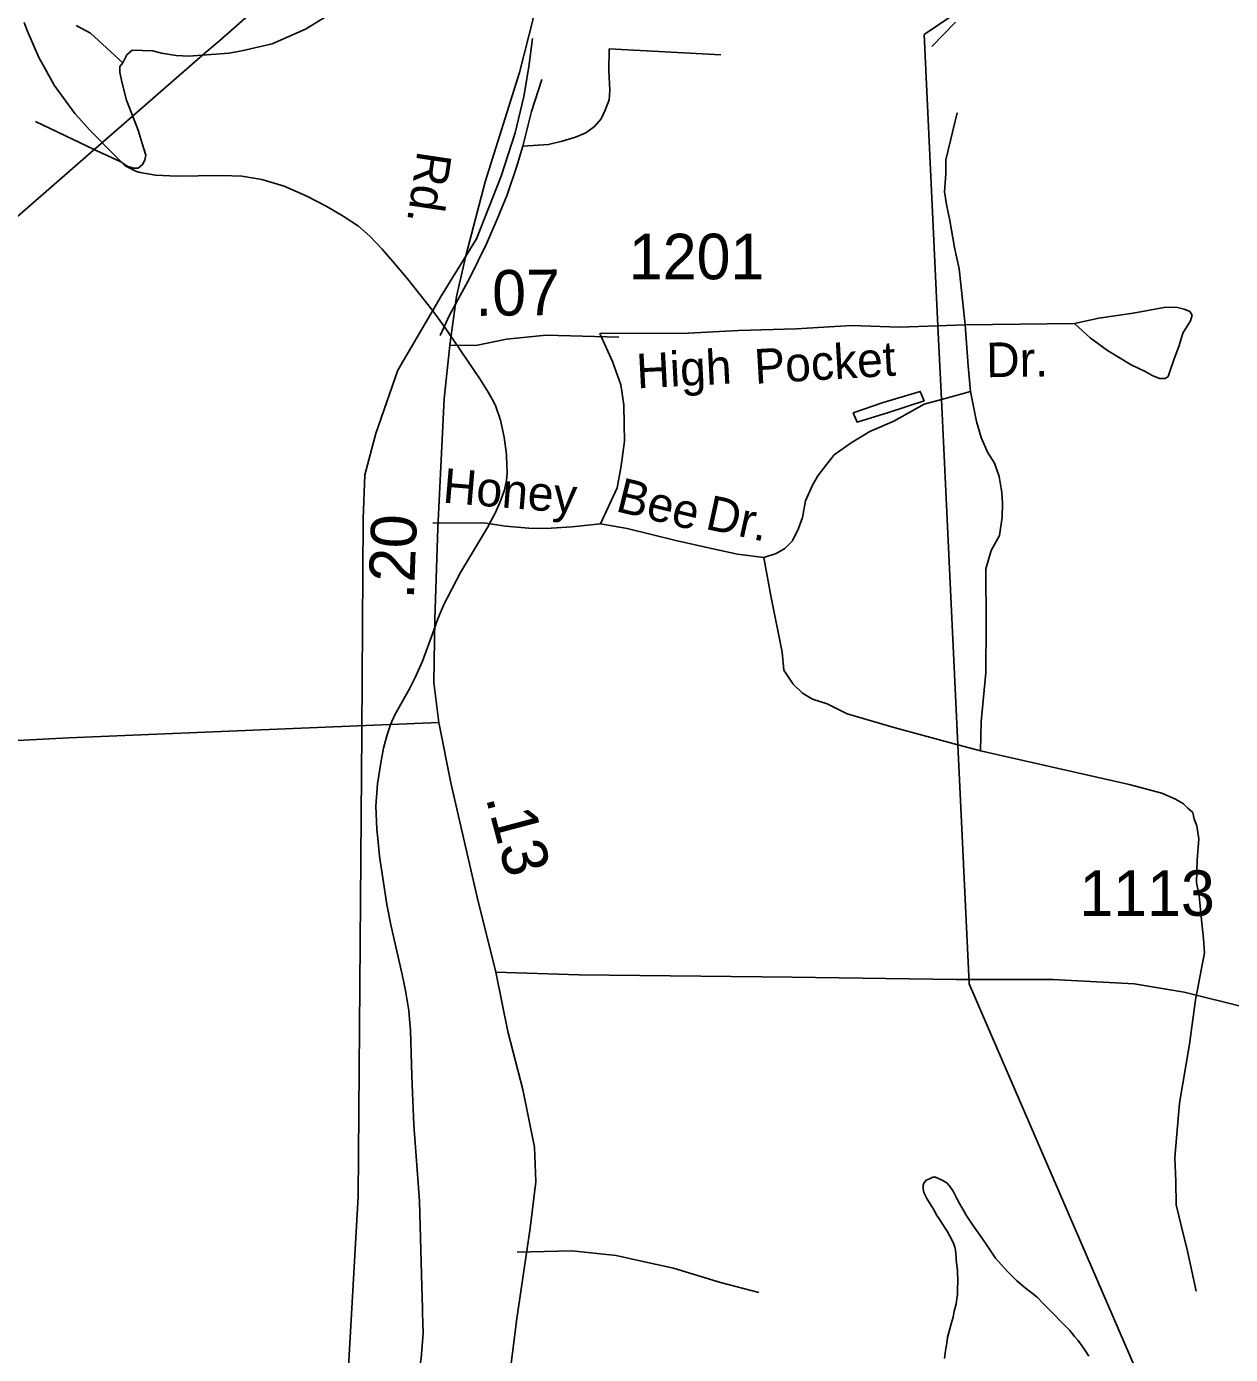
# Model space of a CAD drawing. Extents: x 2001466 to 2224147, y 644118 to 847247.
# Drawn here: x 2045971 to 2049275, y 678885 to 682530 of the extents above; entities that cross this region are included whole.
import ezdxf

# ---------------------------------------------------------------- set-up
doc = ezdxf.new("R2010")
doc.units = 0
for name, color, linetype in [('Exist Hydrographic Misc Water Feature', 7, 'Continuous'), ('Exist Railroad Mainline', 7, 'Continuous'), ('Exist Road Non-System Type 51', 7, 'Continuous'), ('Exist Road Non-System Type 51 Label', 7, 'Continuous'), ('Exist Road Secondary Mileage Hundredths English Label', 7, 'Continuous'), ('Exist Road Secondary Type 51 Attributed', 7, 'Continuous'), ('Exist Road Secondary Type 51 Label', 7, 'Continuous'), ('Exist Road Secondary Type 51 Number Label', 7, 'Continuous'), ('Exist Utilities Electrical Transmission Line', 7, 'Continuous')]:
    doc.layers.add(name, color=color, linetype=linetype)

msp = doc.modelspace()

# ---------------------------------------------------------------- linework, layer by layer
at = {"layer": 'Exist Hydrographic Misc Water Feature'}
for p, q in [((2045964.4, 682541.2), (2045972.8, 682519.2)), ((2046272.4, 682132.1), (2046282.4, 682129.5)), ((2046272.4, 682132.1), (2046282.4, 682129.5)), ((2046839.9, 682009.5), (2046842.8, 682007.8)), ((2047271.8, 681449.6), (2047281.8, 681403)), ((2047283.7, 681263), (2047282.9, 681258))]:
    msp.add_line(p, q, dxfattribs=at)
for points in [[(2045972.8, 682519.2), (2046005, 682445.2), (2046020.4, 682417.4)], [(2045972.8, 682519.2), (2046005, 682445.2), (2046020.4, 682417.4)], [(2046020.4, 682417.4), (2046046.8, 682369.7), (2046103.8, 682291.6), (2046114.5, 682279.6)], [(2046020.4, 682417.4), (2046046.8, 682369.7), (2046103.8, 682291.6), (2046114.5, 682279.6)], [(2046114.5, 682279.6), (2046144, 682246.8), (2046210.4, 682179.4)], [(2046114.5, 682279.6), (2046144, 682246.8), (2046210.4, 682179.4)], [(2046210.4, 682179.4), (2046241.8, 682147.6), (2046272.4, 682132.1)], [(2046210.4, 682179.4), (2046241.8, 682147.6), (2046272.4, 682132.1)], [(2046282.4, 682129.5), (2046324.9, 682122.3), (2046383.9, 682119.3), (2046441.7, 682120.1)], [(2046282.4, 682129.5), (2046324.9, 682122.3), (2046383.9, 682119.3), (2046441.7, 682120.1)], [(2046441.7, 682120.1), (2046505.9, 682121), (2046561.9, 682119.4), (2046578.3, 682116.8)], [(2046441.7, 682120.1), (2046505.9, 682121), (2046561.9, 682119.4), (2046578.3, 682116.8)], [(2046578.3, 682116.8), (2046616.8, 682110.8), (2046677.7, 682091.8), (2046739.9, 682064.8), (2046794.8, 682036.3), (2046839.9, 682009.5)], [(2046578.3, 682116.8), (2046616.8, 682110.8), (2046677.7, 682091.8), (2046739.9, 682064.8), (2046794.8, 682036.3), (2046839.9, 682009.5)], [(2046842.8, 682007.8), (2046881.8, 681981.8), (2046912.7, 681955.1), (2046946.8, 681919.2), (2046975.7, 681885.2)], [(2046842.8, 682007.8), (2046881.8, 681981.8), (2046912.7, 681955.1), (2046946.8, 681919.2), (2046975.7, 681885.2)], [(2046975.7, 681885.2), (2047015.9, 681837.9), (2047086, 681749.9), (2047119.8, 681703.3), (2047145.3, 681665.8)], [(2046975.7, 681885.2), (2047015.9, 681837.9), (2047086, 681749.9), (2047119.8, 681703.3), (2047145.3, 681665.8)], [(2047145.3, 681665.8), (2047214.8, 681563.3), (2047233.4, 681533.4)], [(2047145.3, 681665.8), (2047214.8, 681563.3), (2047233.4, 681533.4)], [(2047233.4, 681533.4), (2047237.9, 681526.5), (2047248.4, 681507.2)], [(2047233.4, 681533.4), (2047237.9, 681526.5), (2047248.4, 681507.2)], [(2048239.6, 681470.2), (2048249.9, 681444.4), (2048335.8, 681470.7), (2048433.8, 681502.9), (2048423.4, 681528.8), (2048321.2, 681498.4), (2048239.6, 681470.2)], [(2047248.4, 681507.2), (2047257.6, 681490.2), (2047271.8, 681449.6)], [(2047248.4, 681507.2), (2047257.6, 681490.2), (2047271.8, 681449.6)], [(2047281.8, 681403), (2047287.8, 681355.3), (2047289.2, 681321.9)], [(2047281.8, 681403), (2047287.8, 681355.3), (2047289.2, 681321.9)], [(2047289.4, 681305.1), (2047288, 681284.1), (2047283.7, 681263)], [(2047289.4, 681305.1), (2047288, 681284.1), (2047283.7, 681263)], [(2047289.2, 681321.9), (2047289.8, 681310.2), (2047289.4, 681305.1)], [(2047289.2, 681321.9), (2047289.8, 681310.2), (2047289.4, 681305.1)], [(2047282.9, 681258), (2047272.8, 681229.9), (2047258, 681196.1), (2047244.9, 681172.6)], [(2047282.9, 681258), (2047272.8, 681229.9), (2047258, 681196.1), (2047244.9, 681172.6)], [(2047244.9, 681172.6), (2047235.7, 681155.3), (2047161.9, 681031.3), (2047125.8, 680962.4)], [(2047244.9, 681172.6), (2047235.7, 681155.3), (2047161.9, 681031.3), (2047125.8, 680962.4)], [(2047125.8, 680962.4), (2047118, 680947.2), (2047106.9, 680921.2)], [(2047125.8, 680962.4), (2047118, 680947.2), (2047106.9, 680921.2)], [(2047106.9, 680921.2), (2047099.7, 680904.6), (2047084.8, 680863)], [(2047106.9, 680921.2), (2047099.7, 680904.6), (2047084.8, 680863)], [(2047084.8, 680863), (2047057.7, 680787.6), (2047037.8, 680742.8)], [(2047084.8, 680863), (2047057.7, 680787.6), (2047037.8, 680742.8)], [(2047037.8, 680742.8), (2047021.8, 680712.3), (2046981.8, 680640.6)], [(2047037.8, 680742.8), (2047021.8, 680712.3), (2046981.8, 680640.6)], [(2046981.8, 680640.6), (2046969.7, 680614), (2046965.2, 680599.8)], [(2046981.8, 680640.6), (2046969.7, 680614), (2046965.2, 680599.8)], [(2046965.2, 680599.8), (2046959.7, 680582.6), (2046956.2, 680569.4)], [(2046965.2, 680599.8), (2046959.7, 680582.6), (2046956.2, 680569.4)], [(2046956.2, 680569.4), (2046950.9, 680548.8), (2046946.8, 680529)], [(2046956.2, 680569.4), (2046950.9, 680548.8), (2046946.8, 680529)], [(2046946.8, 680529), (2046943.7, 680514.8), (2046934.1, 680451.1), (2046929.8, 680390.3), (2046931.8, 680326.1), (2046934.5, 680301.2)], [(2046946.8, 680529), (2046943.7, 680514.8), (2046934.1, 680451.1), (2046929.8, 680390.3), (2046931.8, 680326.1), (2046934.5, 680301.2)], [(2046934.5, 680301.2), (2046939.8, 680252.9), (2046959.7, 680119.8), (2046970.6, 680063.8), (2047001.5, 679928.2), (2047006.2, 679905.9)], [(2046934.5, 680301.2), (2046939.8, 680252.9), (2046959.7, 680119.8), (2046970.6, 680063.8), (2047001.5, 679928.2), (2047006.2, 679905.9)], [(2047006.2, 679905.9), (2047012, 679878.3), (2047019.8, 679829.1), (2047022, 679805)], [(2047006.2, 679905.9), (2047012, 679878.3), (2047019.8, 679829.1), (2047022, 679805)], [(2047022, 679805), (2047024.7, 679775.1), (2047028.4, 679649.8)], [(2047022, 679805), (2047024.7, 679775.1), (2047028.4, 679649.8)], [(2047028.4, 679649.8), (2047029.8, 679603.4), (2047033.9, 679514.8), (2047049.7, 679305.4), (2047056.1, 679070.1)], [(2047028.4, 679649.8), (2047029.8, 679603.4), (2047033.9, 679514.8), (2047049.7, 679305.4), (2047056.1, 679070.1)], [(2048490.2, 678873.3), (2048492.3, 678895.4), (2048495.9, 678915.5), (2048498.2, 678931.3), (2048507.8, 678969.2), (2048514, 678987.4), (2048516, 679003.3), (2048522, 679023.5), (2048523.8, 679037.4), (2048525.9, 679049.6), (2048525.9, 679067.4), (2048526.1, 679083.3), (2048526.1, 679093.4), (2048525.9, 679105.2), (2048525.9, 679115.3), (2048521.6, 679143.6), (2048521.6, 679151.3), (2048519.9, 679171.4), (2048517.9, 679179.4), (2048515.8, 679187.5), (2048509.7, 679199.3), (2048503.5, 679211.2), (2048497.6, 679223.4), (2048491.6, 679231.2), (2048485.7, 679241.5), (2048475.6, 679257.2), (2048467.4, 679269.4), (2048461.3, 679281.3), (2048453.5, 679293.4), (2048441.6, 679313.1), (2048433.6, 679329.3), (2048431.6, 679339.3), (2048431.4, 679349.1), (2048433.2, 679355.3), (2048439.3, 679363.3), (2048449.2, 679367.1), (2048457.6, 679371.1), (2048465.2, 679371.1), (2048475.6, 679367.1), (2048483.4, 679363.1), (2048497.4, 679355.3), (2048505.6, 679345.1), (2048513.4, 679333.4), (2048523.6, 679313.2), (2048531.4, 679299.5), (2048543.5, 679277.3), (2048549.5, 679267.5), (2048569.6, 679237.3), (2048587.4, 679211.4), (2048603.8, 679187.5), (2048629.8, 679149.5), (2048661.6, 679113.8), (2048687.9, 679087.5), (2048711.7, 679067.7), (2048731.5, 679051.7), (2048744.1, 679041.7), (2048761.9, 679024), (2048780.1, 679005.8), (2048792, 678993.8), (2048806, 678977.9), (2048822.2, 678962.1), (2048833.7, 678950.2), (2048846.4, 678934.1), (2048856.2, 678924.1), (2048866.1, 678910), (2048876.1, 678895.9), (2048886.2, 678880.2)], [(2047056.1, 679070.1), (2047057.7, 679012.7), (2047057.9, 678998.8)], [(2047056.1, 679070.1), (2047057.7, 679012.7), (2047057.9, 678998.8)], [(2047057.9, 678998.8), (2047058.9, 678944), (2047054, 678873.3), (2047039.7, 678795.8), (2047033.9, 678774.6)], [(2047057.9, 678998.8), (2047058.9, 678944), (2047054, 678873.3), (2047039.7, 678795.8), (2047033.9, 678774.6)]]:
    msp.add_lwpolyline(points, dxfattribs=at)
at = {"layer": 'Exist Railroad Mainline'}
for points in [[(2047101.9, 681779.1), (2047106.6, 681787.1), (2047205.5, 681947.8), (2047273.4, 682119.8), (2047311.4, 682238), (2047335.3, 682338), (2047349.1, 682420.1), (2047359.1, 682497.7)], [(2046890.6, 680593), (2046895.1, 681178.8), (2046898.9, 681299.7), (2046929.1, 681413), (2046989.5, 681586.9), (2047101.9, 681779.1)], [(2047327.9, 674874), (2047221.5, 675019.8), (2047087.4, 675229.7), (2046987.3, 675411.8), (2046917.3, 675571.8), (2046879.1, 675775.8), (2046839, 676027.8), (2046823.8, 676143.3), (2046806.8, 676271.8), (2046768.8, 676576), (2046732.5, 676936), (2046686.3, 677280.1), (2046654.1, 677554.2), (2046646.1, 677674.1), (2046649.6, 677864.9), (2046683.6, 678023.6), (2046717.6, 678148.3), (2046774.2, 678288.1), (2046815.8, 678420.3), (2046838.4, 678560.1), (2046881, 679318.8), (2046890.6, 680593)]]:
    msp.add_lwpolyline(points, dxfattribs=at)
at = {"layer": 'Exist Road Non-System Type 51'}
for p, q in [((2046179.1, 682182), (2045995.8, 682269.3)), ((2048472, 681708.3), (2048546.7, 681711)), ((2048546.7, 681711), (2048846.8, 681714.9)), ((2048481.6, 681506.5), (2048561, 681528.7)), ((2048588.9, 680542.1), (2048526.7, 680558.7))]:
    msp.add_line(p, q, dxfattribs=at)
for points in [[(2046464.9, 682452.4), (2046490.6, 682454), (2046526.2, 682457.2), (2046561.5, 682463.6), (2046645, 682482.9), (2046736.5, 682523), (2046816.7, 682572.8), (2046877.7, 682601.7), (2046935.5, 682624.2), (2046974, 682637.1), (2047025.4, 682645.1), (2047070.4, 682651.5), (2047112.1, 682654.8), (2047161.9, 682651.5), (2047230.9, 682637.1), (2047370.6, 682603.3)], [(2046106.9, 682533.1), (2046146.4, 682512.3), (2046235.1, 682430.5)], [(2048520, 682542.6), (2048454.8, 682475.3)], [(2046464.9, 682452.4), (2046416.7, 682449.2), (2046381.4, 682450.8), (2046341.3, 682457.2), (2046317.2, 682463.6), (2046261, 682465.2), (2046246.6, 682452.4)], [(2047332.7, 682201.6), (2047402.8, 682206.2), (2047441, 682215.4), (2047477.2, 682226.7), (2047505.4, 682238.1), (2047529.8, 682255.6), (2047548.2, 682277.2), (2047558.7, 682301), (2047569.3, 682328.8), (2047571.8, 682354.8), (2047568.9, 682410.8), (2047570.1, 682468.8), (2047875.8, 682452.6)], [(2046246.6, 682452.4), (2046235.1, 682430.5), (2046226.9, 682420.6), (2046226.6, 682404.6), (2046232, 682378.5), (2046245, 682328.3), (2046270.9, 682262)], [(2047332.7, 682201.6), (2047356.6, 682297.1), (2047384.8, 682385)], [(2048524.6, 682293.4), (2048493.9, 682164), (2048493.2, 682126), (2048490.1, 682076.1), (2048495.4, 682042), (2048504.5, 681997.8), (2048517, 681923.6), (2048529.8, 681865.3), (2048535, 681823.2), (2048546.7, 681711)], [(2046270.9, 682262), (2046277.3, 682245.6), (2046288.6, 682209.4), (2046297.9, 682177.2), (2046295.7, 682163.2), (2046289.4, 682151.4), (2046277.2, 682141.6), (2046265.2, 682141.8), (2046249.3, 682146.2), (2046229.6, 682158.6), (2046180, 682181.6), (2046179.1, 682182)], [(2047106.1, 681682.2), (2047131.2, 681737.7), (2047187.3, 681840.6), (2047233.2, 681933.6), (2047262.6, 682001), (2047290, 682068.5), (2047315.5, 682144), (2047332.7, 682201.6)], [(2048846.8, 681714.9), (2048890, 681676), (2048937.3, 681641), (2049002.5, 681601.7), (2049040.1, 681582.9), (2049059.9, 681572.5), (2049079.7, 681564.1), (2049095.7, 681563.8), (2049103.8, 681569.6), (2049108.1, 681583.6), (2049118.8, 681615.3), (2049133.6, 681655), (2049144.3, 681688.8), (2049164.9, 681722.4), (2049169.3, 681738.3), (2049163.5, 681748.4), (2049147.6, 681754.8), (2049129.7, 681759.1), (2049097.7, 681759.8), (2049007.4, 681743.6), (2048913.1, 681729.5), (2048846.8, 681714.9)], [(2047544.2, 681687.3), (2047786.2, 681688.4), (2047924.4, 681695.6), (2048082.5, 681700.4), (2048234.7, 681709.3), (2048366.6, 681704.6), (2048472, 681708.3)], [(2048546.7, 681711), (2048554.4, 681598.8), (2048561, 681528.7)], [(2047544.2, 681687.3), (2047578.7, 681610.6), (2047601.3, 681546.2), (2047610.2, 681492), (2047611.1, 681437.9), (2047612.2, 681391.9), (2047602.8, 681324.1), (2047591.6, 681264.3), (2047545.6, 681165.3)], [(2048561, 681528.7), (2048577.3, 681446.3), (2048590.4, 681402.1), (2048607.6, 681361.7), (2048627, 681331.3), (2048640.2, 681295.1), (2048647.3, 681250.9), (2048648.7, 681220.9), (2048648, 681182.9), (2048640.9, 681133), (2048618.1, 681091.5), (2048603.1, 681041.8), (2048604, 680889.8), (2048603.3, 680755.8), (2048590.5, 680622.1), (2048588.9, 680542.1)], [(2047993.7, 681072.2), (2048027.9, 681083.5), (2048052.2, 681097), (2048072.6, 681118.6), (2048089.3, 681152.2), (2048099.9, 681182), (2048108.9, 681227.8), (2048127.8, 681271.5), (2048142.3, 681297.2), (2048166.9, 681328.7), (2048187.4, 681354.2), (2048234.1, 681387.3), (2048284.7, 681418.3), (2048351.3, 681446.9), (2048434.3, 681493.2), (2048481.6, 681506.5)], [(2047085.6, 681166.6), (2047225.6, 681167.8), (2047285.5, 681158.6), (2047349.3, 681153.3), (2047397.3, 681152.3), (2047467.4, 681156.9), (2047545.6, 681165.3)], [(2047545.6, 681165.3), (2047619.3, 681151.8), (2047752.7, 681119.1), (2047850.2, 681097.1), (2047921.9, 681081.6), (2047993.7, 681072.2)], [(2048526.7, 680558.7), (2048354.2, 680604.9), (2048223, 680643.5), (2048167.5, 680670.6), (2048127.8, 680683.5), (2048100.1, 680700), (2048074.6, 680724.5), (2048049.4, 680763), (2048044.4, 680813.1), (2048013.6, 680967.8), (2047993.7, 681072.2)], [(2049179, 679858.1), (2049203.6, 679987.6), (2049200.4, 680025.7), (2049195.5, 680077.8), (2049188.8, 680143.9), (2049181.5, 680180.1), (2049182.8, 680242), (2049188, 680299.9), (2049182.7, 680336), (2049175.1, 680354.2), (2049171.5, 680372.3), (2049157.7, 680384.5), (2049146, 680396.8), (2049124.2, 680409.2), (2049086.5, 680426), (2048997, 680449.8), (2048588.9, 680542.1)], [(2049179, 679858.1), (2049162.5, 679736.4), (2049135.2, 679575), (2049122.2, 679425.3), (2049124.8, 679359.2), (2049125.5, 679295.2), (2049140.3, 679234.9), (2049156.9, 679168.5), (2049180.7, 679058.1)], [(2047316.9, 679165.9), (2047467, 679168.9), (2047588.7, 679156.4), (2047666.3, 679138.8), (2047746, 679121.2), (2047875.2, 679082.6), (2047980.6, 679054.4)]]:
    msp.add_lwpolyline(points, dxfattribs=at)
at = {"layer": 'Exist Road Secondary Type 51 Attributed'}
for points in [[(2046734.7, 687467.8), (2046909.4, 687051.6), (2047030.8, 686748.5), (2047102.6, 686562.5), (2047145.8, 686423.1), (2047182.3, 686268.9), (2047289.4, 685751.3), (2047358.5, 685379.5), (2047440.9, 685001.3), (2047492.1, 684709.8), (2047555.4, 684409.8), (2047589.2, 684257.6), (2047587.1, 684164.7), (2047545.4, 683896.4), (2047487.3, 683516.1), (2047443.5, 683183.4), (2047414, 682927.7), (2047391.8, 682732.3), (2047363.3, 682559.1), (2047323.7, 682403.8), (2047229.2, 682103.8), (2047176.5, 681901), (2047151.1, 681789), (2047132.1, 681655.9)], [(2047132.1, 681655.9), (2047116.8, 681508), (2047099.4, 681154.2), (2047091, 680902.8), (2047088.8, 680729.5), (2047102.6, 680619.7)], [(2047132.1, 681655.9), (2047203.4, 681654.9), (2047287.8, 681671.8), (2047396.6, 681683.4), (2047596.1, 681677.1)], [(2047102.6, 680619.7), (2046703, 680602.9), (2046086.6, 680577.5), (2045519.7, 680547.9), (2045200.9, 680541.6), (2044709, 680564.8), (2044293.1, 680575.4), (2044013.4, 680602.9), (2043521.5, 680689.5), (2042997.9, 680784.5), (2042529.7, 680879.6)], [(2047102.6, 680619.7), (2047135.3, 680453.8), (2047207.6, 680140.1), (2047258.8, 679934.1)], [(2047258.8, 679934.1), (2047292.1, 679771.4), (2047333.2, 679611.9), (2047364.9, 679453.5), (2047368.6, 679358.4), (2047352.7, 679231.7), (2047316.3, 678983.4), (2047292.1, 678788), (2047268.3, 678583.1), (2047265.1, 678408.8), (2047274.6, 678263), (2047300.5, 678110.9), (2047366.5, 677848.9), (2047423.5, 677608.1), (2047457.3, 677392.6), (2047473.1, 677158.1), (2047498.4, 676910.9), (2047530.1, 676585.6), (2047544.9, 676378.5)], [(2049313, 679838), (2049147.3, 679879.2), (2049010, 679902.4), (2048787.3, 679914.1), (2048521.8, 679914.1), (2048071.6, 679920.4), (2047486.8, 679926.7), (2047258.8, 679934.1)]]:
    msp.add_lwpolyline(points, dxfattribs=at)
at = {"layer": 'Exist Utilities Electrical Transmission Line'}
for p, q in [((2046461.3, 682457.7), (2046239.2, 682264.1)), ((2046239.2, 682264.1), (2046147.4, 682184.1)), ((2048472, 681708.3), (2048481.6, 681506.5)), ((2048481.6, 681506.5), (2048526.7, 680558.7)), ((2048526.7, 680558.7), (2048557.8, 679903.7))]:
    msp.add_line(p, q, dxfattribs=at)
for points in [[(2046461.3, 682457.7), (2046501.1, 682492.3), (2047432.9, 683313.4)], [(2049411.6, 683170), (2048434, 682508.2), (2048472, 681708.3)], [(2046147.4, 682184.1), (2045025, 681205.7), (2044277.3, 680537.6)], [(2048557.8, 679903.7), (2048557.9, 679902.1), (2049060.2, 678740.1), (2049118.3, 677993.1)]]:
    msp.add_lwpolyline(points, dxfattribs=at)

# ---------------------------------------------------------------- texts
at = {"layer": 'Exist Road Non-System Type 51 Label'}
for s, rotation, p in [('Pocket', 3.3498, (2047970.5, 681549.4)), ('Dr.', 0.746, (2048605, 681567.5)), ('High', 2.9814, (2047646.8, 681536.7)), ('Honey', 355.2592, (2047111.1, 681223.5)), ('Bee', 346.2178, (2047584.7, 681200.5)), ('Dr.', 347.8329, (2047830.6, 681151.7))]:
    msp.add_text(s, height=95, rotation=rotation, dxfattribs=at).set_placement(p)
at = {"layer": 'Exist Road Secondary Mileage Hundredths English Label'}
for s, rotation, p in [('.07', 0.6676, (2047202.9, 681735.8)), ('.20', 87.8073, (2047033.6, 680956.5)), ('.13', 284.8742, (2047230.4, 680413.4))]:
    msp.add_text(s, height=125, rotation=rotation, dxfattribs=at).set_placement(p)
at = {"layer": 'Exist Road Secondary Type 51 Label'}
msp.add_text('Rd.', height=95, rotation=261.4519, dxfattribs=at).set_placement((2047044.2, 682191.4))
at = {"layer": 'Exist Road Secondary Type 51 Number Label'}
for s, p in [('1201', (2047623.7, 681836.5)), ('1113', (2048859.9, 680088.8))]:
    msp.add_text(s, height=125, dxfattribs=at).set_placement(p)

doc.saveas('drawing.dxf')
